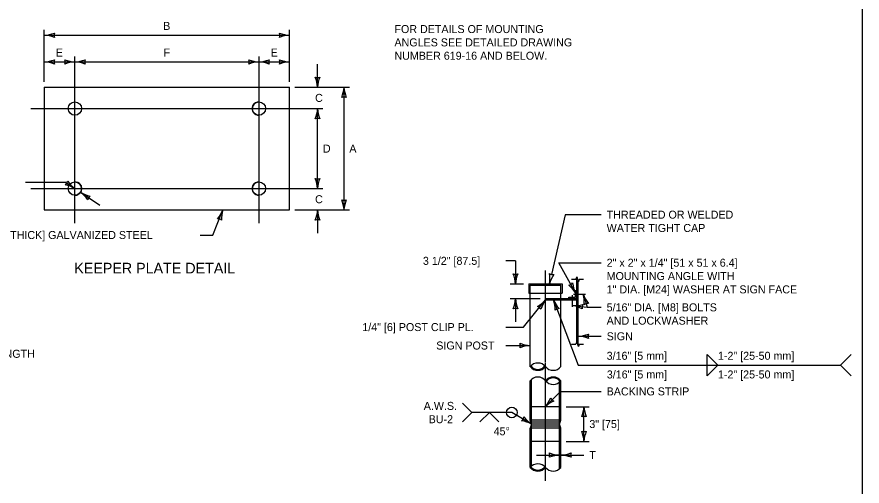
# Model space of a CAD drawing. Extents: x 49991 to 81321, y 49988 to 50028.
# Drawn here: x 50010.41 to 50016.75, y 49992.49 to 49996.01 of the extents above; entities that cross this region are included whole.
import ezdxf

# ---------------------------------------------------------------- set-up
doc = ezdxf.new("R2010")
doc.units = 0
for name, color, linetype in [('Level 1', 7, 'Continuous'), ('Level 2', 7, 'Continuous'), ('Level 3', 7, 'Continuous'), ('Level 4', 7, 'Continuous'), ('Level 5', 7, 'Continuous'), ('Level 6', 7, 'Continuous')]:
    doc.layers.add(name, color=color, linetype=linetype)

msp = doc.modelspace()

# ---------------------------------------------------------------- linework, layer by layer
at = {"layer": 'Level 1'}
for p, q in [((50010.6168, 49995.4787), (50012.4568, 49995.4787)), ((50010.6168, 49995.4787), (50010.6168, 49994.5587)), ((50012.4568, 49994.5587), (50012.4568, 49995.4787)), ((50010.6168, 49994.5587), (50012.4568, 49994.5587)), ((50014.6111, 49993.566), (50014.6111, 49994.0526)), ((50014.2511, 49994.0033), (50014.5011, 49994.0033)), ((50014.2511, 49994.0033), (50014.2511, 49993.9333)), ((50014.5011, 49994.0033), (50014.5011, 49993.9333)), ((50014.6211, 49993.5378), (50014.6211, 49994.0244)), ((50014.2511, 49993.9333), (50014.5011, 49993.9333)), ((50014.2611, 49993.3829), (50014.2611, 49993.9333)), ((50014.2611, 49993.3829), (50014.2611, 49993.9333)), ((50014.2611, 49993.3829), (50014.2611, 49993.9333)), ((50014.2611, 49993.3829), (50014.2611, 49993.9333)), ((50014.4911, 49993.3832), (50014.4911, 49993.9333)), ((50014.5857, 49993.9255), (50014.6761, 49993.9255)), ((50014.6011, 49993.9033), (50014.6011, 49993.9533)), ((50014.6011, 49993.9533), (50014.6111, 49993.9533)), ((50014.3761, 49993.8933), (50014.6111, 49993.8933)), ((50014.3761, 49993.8833), (50014.3761, 49993.8933)), ((50014.3761, 49993.8833), (50014.6111, 49993.8833)), ((50014.5511, 49993.9033), (50014.6011, 49993.9033)), ((50014.5511, 49993.8933), (50014.5511, 49993.9033)), ((50014.5785, 49993.8322), (50014.5785, 49993.9189)), ((50014.2611, 49992.9827), (50014.2611, 49993.2777)), ((50014.4911, 49992.9827), (50014.491, 49993.2778)), ((50014.4911, 49992.9827), (50014.2611, 49992.9827)), ((50014.2711, 49992.9527), (50014.2611, 49992.9827)), ((50014.4811, 49992.9527), (50014.4911, 49992.9827)), ((50014.2711, 49992.9527), (50014.2611, 49992.9227)), ((50014.4911, 49992.9227), (50014.2611, 49992.9227)), ((50014.2611, 49992.6274), (50014.2611, 49992.9227)), ((50014.4811, 49992.9677), (50014.2711, 49992.9677)), ((50014.4811, 49992.9527), (50014.2711, 49992.9527)), ((50014.4811, 49992.9377), (50014.2711, 49992.9377)), ((50014.4911, 49992.9227), (50014.4811, 49992.9527)), ((50014.4911, 49992.6276), (50014.4911, 49992.9227))]:
    msp.add_line(p, q, dxfattribs=at)
msp.add_lwpolyline([(49999.3835, 49998.9992), (50016.7501, 49998.9992), (50016.7501, 49987.7988), (49999.3835, 49987.7988)], close=True, dxfattribs=at)
for centre in [(50010.8468, 49995.3187), (50012.2268, 49995.3187), (50010.8468, 49994.7187), (50012.2268, 49994.7187)]:
    msp.add_circle(centre, 0.05, dxfattribs=at)
for centre, radius, start, end in [((50012.2268, 49995.3187), 0.05, 90, 273.45431), ((50010.8468, 49994.7187), 0.05, 270, 93.45431), ((50012.2268, 49994.7187), 0.05, 90, 273.45431), ((50014.3186, 49993.3362), 0.0741, 39.17071, 140.92889), ((50014.3186, 49993.4298), 0.0741, 219.17071, 320.82929), ((50014.3186, 49993.4298), 0.0673, 218.24875, 321.75125), ((50014.4335, 49993.4298), 0.0741, 219.17071, 321.00882), ((50014.3185, 49993.231), 0.0741, 39.11604, 140.90495), ((50014.4335, 49993.231), 0.0741, 39.11604, 140.88396), ((50014.4335, 49993.231), 0.0672, 38.18255, 141.81745), ((50014.4335, 49993.3245), 0.0741, 219.11604, 320.88396), ((50014.3186, 49992.5806), 0.0741, 39.17071, 140.85983), ((50014.3186, 49992.6742), 0.0741, 219.14017, 320.82929), ((50014.3186, 49992.6742), 0.0673, 218.24684, 321.74095), ((50014.4335, 49992.6742), 0.0741, 219.17071, 321.0128)]:
    msp.add_arc(centre, radius, start, end, dxfattribs=at)
at = {"layer": 'Level 3'}
for p, q in [((50010.6168, 49995.5187), (50010.6168, 49995.9087)), ((50012.4568, 49995.5187), (50012.4568, 49995.9087)), ((50010.6168, 49995.8687), (50012.4568, 49995.8687)), ((50010.6168, 49995.6687), (50010.8468, 49995.6687)), ((50010.8468, 49995.6687), (50012.2282, 49995.6687)), ((50012.2282, 49995.6687), (50012.4568, 49995.6687)), ((50012.6664, 49995.4787), (50012.6664, 49995.6521)), ((50012.4968, 49995.4787), (50012.9047, 49995.4787)), ((50012.8647, 49994.5587), (50012.8647, 49995.4787)), ((50012.6664, 49994.7187), (50012.6664, 49995.3187)), ((50010.475, 49994.7658), (50010.776, 49994.7658)), ((50010.776, 49994.7658), (50010.8468, 49994.7187)), ((50010.8884, 49994.691), (50011.0328, 49994.595)), ((50011.8813, 49994.3703), (50011.9562, 49994.5587)), ((50012.4968, 49994.5587), (50012.9047, 49994.5587)), ((50012.6664, 49994.5587), (50012.6664, 49994.3853)), ((50014.5229, 49994.523), (50014.4219, 49994.075)), ((50014.7945, 49994.523), (50014.5229, 49994.523)), ((50011.7853, 49994.3703), (50011.8813, 49994.3703)), ((50014.1511, 49994.1767), (50014.0787, 49994.1767)), ((50014.1511, 49994.1767), (50014.1511, 49994.0033)), ((50014.601, 49993.936), (50014.4767, 49994.1626)), ((50014.4767, 49994.1626), (50014.7945, 49994.1626)), ((50014.1111, 49994.0033), (50014.2111, 49994.0033)), ((50014.6596, 49993.9255), (50014.6895, 49993.828)), ((50014.1111, 49993.8933), (50014.3361, 49993.8933)), ((50014.1511, 49993.8933), (50014.1511, 49993.7199)), ((50014.2115, 49993.6799), (50014.3761, 49993.8833)), ((50014.4365, 49993.8833), (50014.62, 49993.3946)), ((50014.5785, 49993.8425), (50014.6895, 49993.828)), ((50014.6895, 49993.828), (50014.7945, 49993.828)), ((50014.0787, 49993.6799), (50014.2115, 49993.6799)), ((50014.6211, 49993.6109), (50014.7945, 49993.6109)), ((50014.0787, 49993.5416), (50014.2611, 49993.5417)), ((50014.0787, 49993.5416), (50014.1588, 49993.5416)), ((50015.5891, 49993.3146), (50015.5891, 49993.4746)), ((50015.5891, 49993.4746), (50015.6691, 49993.3946)), ((50016.5872, 49993.3946), (50016.6672, 49993.4746)), ((50014.62, 49993.3946), (50016.5872, 49993.3946)), ((50015.5891, 49993.3146), (50015.6691, 49993.3946)), ((50016.5872, 49993.3946), (50016.6672, 49993.3146)), ((50014.4877, 49993.1974), (50014.3731, 49993.0827)), ((50014.4877, 49993.1974), (50014.7945, 49993.1974)), ((50013.8231, 49993.0389), (50013.7524, 49993.1096)), ((50013.8231, 49993.0389), (50013.7524, 49992.9682)), ((50014.1237, 49993.0389), (50013.8231, 49993.0389)), ((50013.9547, 49993.0389), (50013.884, 49992.9682)), ((50014.0254, 49992.9682), (50013.9547, 49993.0389)), ((50014.2711, 49992.9527), (50014.1237, 49993.0389)), ((50014.5311, 49993.0827), (50014.7045, 49993.0827)), ((50014.6645, 49992.8227), (50014.6645, 49993.0827)), ((50014.5311, 49992.8227), (50014.7045, 49992.8227)), ((50014.3077, 49992.7202), (50014.4811, 49992.7202)), ((50014.4911, 49992.7202), (50014.6645, 49992.7202))]:
    msp.add_line(p, q, dxfattribs=at)
msp.add_circle((50014.1237, 49993.0389), 0.04, dxfattribs=at)
for centre, radius, start, end in [((50010.6053, 49996.1014), 0.233, 272.82731, 292.07716), ((50010.745, 49995.8687), 0.0548, 162.13882, 197.86118), ((50012.4659, 49996.0908), 0.2223, 247.45601, 267.63952), ((50012.3286, 49995.8687), 0.0548, 342.13882, 17.86118), ((50010.6076, 49995.6466), 0.2223, 67.45601, 87.63952), ((50012.4683, 49995.636), 0.233, 92.82731, 112.07716), ((50010.6053, 49995.9014), 0.233, 272.82731, 292.07716), ((50010.6076, 49995.4466), 0.2223, 67.45601, 87.63952), ((50010.745, 49995.6687), 0.0548, 162.13882, 197.86118), ((50010.8559, 49995.8908), 0.2223, 247.45601, 267.63952), ((50010.7186, 49995.6687), 0.0548, 342.13882, 17.86118), ((50010.8583, 49995.436), 0.233, 92.82731, 112.07716), ((50010.8353, 49995.9014), 0.233, 272.82731, 292.07716), ((50010.8376, 49995.4466), 0.2223, 67.45601, 87.63952), ((50010.975, 49995.6687), 0.0548, 162.13882, 197.86118), ((50012.2359, 49995.8908), 0.2223, 247.45601, 267.63952), ((50012.0986, 49995.6687), 0.0548, 342.13882, 17.86118), ((50012.2383, 49995.436), 0.233, 92.82731, 112.07716), ((50012.2153, 49995.9014), 0.233, 272.82731, 292.07716), ((50012.2176, 49995.4466), 0.2223, 67.45601, 87.63952), ((50012.355, 49995.6687), 0.0548, 162.13882, 197.86118), ((50012.4659, 49995.8908), 0.2223, 247.45601, 267.63952), ((50012.3286, 49995.6687), 0.0548, 342.13882, 17.86118), ((50012.4683, 49995.436), 0.233, 92.82731, 112.07716), ((50012.6664, 49995.6069), 0.0548, 252.13882, 287.86118), ((50012.4337, 49995.4672), 0.233, 2.82731, 22.07716), ((50012.8885, 49995.4695), 0.2223, 157.45601, 177.63952), ((50012.6426, 49995.4879), 0.2223, 337.45601, 357.63952), ((50013.0974, 49995.4902), 0.233, 182.82731, 202.07716), ((50012.8647, 49995.3505), 0.0548, 72.13882, 107.86118), ((50012.4443, 49995.3279), 0.2223, 337.45601, 357.63952), ((50012.8991, 49995.3302), 0.233, 182.82731, 202.07716), ((50012.6664, 49995.1905), 0.0548, 72.13882, 107.86118), ((50010.74, 49994.7897), 0.0548, 308.52207, 344.24443), ((50010.7275, 49994.5185), 0.233, 59.21056, 78.46041), ((50010.9774, 49994.8986), 0.2223, 213.83926, 234.02277), ((50012.6664, 49994.8469), 0.0548, 252.13882, 287.86118), ((50012.4337, 49994.7072), 0.233, 2.82731, 22.07716), ((50012.8885, 49994.7095), 0.2223, 157.45601, 177.63952), ((50010.7578, 49994.511), 0.2223, 33.85278, 54.03628), ((50011.0076, 49994.8912), 0.233, 239.22408, 258.47393), ((50010.9952, 49994.62), 0.0548, 128.53558, 164.25794), ((50012.8647, 49994.6869), 0.0548, 252.13882, 287.86118), ((50012.632, 49994.5472), 0.233, 2.82731, 22.07716), ((50013.0868, 49994.5495), 0.2223, 157.45601, 177.63952), ((50011.74, 49994.6457), 0.233, 318.83632, 338.08617), ((50012.1691, 49994.4947), 0.2223, 163.27396, 183.45747), ((50012.4443, 49994.5679), 0.2223, 337.45601, 357.63952), ((50012.8991, 49994.5702), 0.233, 182.82731, 202.07716), ((50011.9142, 49994.4375), 0.0548, 53.0523, 88.77466), ((50012.6664, 49994.4305), 0.0548, 72.13882, 107.86118), ((50014.1511, 49994.1315), 0.0548, 252.13882, 287.86118), ((50013.9183, 49993.9918), 0.233, 2.82731, 22.07716), ((50014.3732, 49993.9942), 0.2223, 157.45601, 177.63952), ((50014.1762, 49994.0433), 0.233, 350.12207, 9.37192), ((50014.6204, 49993.9455), 0.2223, 144.75077, 164.93428), ((50014.4339, 49994.1284), 0.0548, 239.43358, 275.15594), ((50014.5394, 49994.0483), 0.0548, 280.87536, 316.59773), ((50014.4025, 49993.8139), 0.233, 31.56386, 50.81371), ((50014.8002, 49994.0347), 0.2223, 186.19256, 206.37606), ((50014.4445, 49993.8691), 0.2223, 354.51079, 14.6943), ((50014.8787, 49994.0048), 0.233, 199.88209, 219.13194), ((50013.9289, 49993.9025), 0.2223, 337.45601, 357.63952), ((50014.3838, 49993.9048), 0.233, 182.82731, 202.07716), ((50014.2091, 49994.0302), 0.2223, 298.48321, 318.66671), ((50014.5642, 49993.7459), 0.233, 143.85451, 163.10436), ((50014.2253, 49993.8138), 0.2223, 358.03153, 18.21504), ((50014.6503, 49993.9759), 0.233, 203.40283, 222.65268), ((50014.6972, 49993.803), 0.0548, 89.1936, 124.91596), ((50014.1511, 49993.7651), 0.0548, 72.13882, 107.86118), ((50014.2954, 49993.7837), 0.0548, 33.16601, 68.88837), ((50014.4816, 49993.7633), 0.0548, 92.71434, 128.4367), ((50014.5972, 49994.0748), 0.233, 265.3948, 284.64465), ((50014.5406, 49993.6234), 0.2223, 60.0235, 80.20701), ((50014.7056, 49993.8259), 0.0548, 154.70631, 190.42867), ((50014.6096, 49993.8436), 0.233, 272.82731, 292.07716), ((50014.6119, 49993.3888), 0.2223, 67.45601, 87.63952), ((50014.7493, 49993.6109), 0.0548, 162.13882, 197.86118), ((50014.2702, 49993.7638), 0.2223, 247.46964, 267.65315), ((50014.1328, 49993.5416), 0.0548, 342.15245, 17.87481), ((50014.2726, 49993.309), 0.233, 92.84094, 112.09079), ((50014.2003, 49993.2391), 0.233, 317.85337, 337.10322), ((50014.5237, 49992.9193), 0.2223, 112.48207, 132.66558), ((50014.4637, 49993.1734), 0.0548, 207.16487, 242.88724), ((50014.4423, 49993.0919), 0.2223, 337.45601, 357.63952), ((50014.8972, 49993.0942), 0.233, 182.82731, 202.07716), ((50014.1604, 49993.0175), 0.0548, 311.81958, 347.54194), ((50014.1635, 49992.746), 0.233, 62.50807, 81.75793), ((50014.3911, 49993.1399), 0.2223, 217.13678, 237.32028), ((50014.6645, 49992.9545), 0.0548, 72.13882, 107.86118), ((50014.6645, 49992.9509), 0.0548, 252.13882, 287.86118), ((50014.4317, 49992.8112), 0.233, 2.82731, 22.07716), ((50014.8866, 49992.8136), 0.2223, 157.45601, 177.63952), ((50014.4902, 49992.9424), 0.2223, 247.45601, 267.63952), ((50014.3528, 49992.7202), 0.0548, 342.13882, 17.86118), ((50014.4925, 49992.4875), 0.233, 92.82731, 112.07716), ((50014.4796, 49992.9529), 0.233, 272.82731, 292.07716), ((50014.4819, 49992.4981), 0.2223, 67.45601, 87.63952), ((50014.6193, 49992.7202), 0.0548, 162.13882, 197.86118)]:
    msp.add_arc(centre, radius, start, end, dxfattribs=at)
at = {"layer": 'Level 4'}
for p, q in [((50014.2611, 49993.9333), (50014.2611, 49993.9933)), ((50014.2611, 49993.9933), (50014.4911, 49993.9933)), ((50014.4911, 49993.9333), (50014.4911, 49993.9933)), ((50014.6111, 49993.8833), (50014.6111, 49993.8933)), ((50014.2711, 49992.6397), (50014.2711, 49993.2873)), ((50014.4811, 49992.6204), (50014.4811, 49993.2681)), ((50014.4811, 49993.0827), (50014.2711, 49993.0827)), ((50014.4811, 49992.8227), (50014.2711, 49992.8227))]:
    msp.add_line(p, q, dxfattribs=at)
at = {"layer": 'Level 5'}
for p, q in [((50010.8468, 49994.4587), (50010.8468, 49995.7087)), ((50012.2268, 49995.7087), (50012.2268, 49994.4587)), ((50010.5168, 49995.3187), (50012.7064, 49995.3187)), ((50010.5168, 49994.7187), (50012.7064, 49994.7187)), ((50014.3761, 49993.4194), (50014.3761, 49994.1033)), ((50014.3761, 49992.5274), (50014.3761, 49993.415))]:
    msp.add_line(p, q, dxfattribs=at)
at = {"layer": 'Level 6'}
for p, q in [((50014.6096, 49994.0568), (50014.6031, 49994.0385)), ((50014.6096, 49994.0568), (50014.6161, 49994.0385)), ((50014.5711, 49994.0385), (50014.6031, 49994.0385)), ((50014.6161, 49994.0385), (50014.6226, 49994.0202)), ((50014.6291, 49994.0385), (50014.6226, 49994.0202)), ((50014.6291, 49994.0385), (50014.6611, 49994.0385)), ((50014.5711, 49993.5519), (50014.6031, 49993.5519)), ((50014.6096, 49993.5702), (50014.6031, 49993.5519)), ((50014.6096, 49993.5702), (50014.6161, 49993.5519)), ((50014.6161, 49993.5519), (50014.6226, 49993.5336)), ((50014.6291, 49993.5519), (50014.6226, 49993.5336)), ((50014.6291, 49993.5519), (50014.6611, 49993.5519))]:
    msp.add_line(p, q, dxfattribs=at)

# ---------------------------------------------------------------- texts
at = {"layer": 'Level 2'}
for s, height, p in [('B', 0.06, (50011.5091, 49995.9087)), ('FOR DETAILS OF MOUNTING', 0.06, (50013.243, 49995.8851)), ('ANGLES SEE DETAILED DRAWING', 0.06, (50013.243, 49995.7851)), ('E', 0.06, (50010.7031, 49995.7087)), ('F', 0.06, (50011.5113, 49995.7087)), ('E', 0.06, (50012.3145, 49995.7087)), ('NUMBER 619-16 AND BELOW.', 0.06, (50013.243, 49995.6851)), ('C', 0.06, (50012.6479, 49995.3687)), ('D', 0.06, (50012.7064, 49994.9886)), ('A', 0.06, (50012.9047, 49994.9887)), ('C', 0.06, (50012.6479, 49994.6087)), ('THREADED OR WELDED', 0.06, (50014.8345, 49994.493)), ('WATER TIGHT CAP', 0.06, (50014.8345, 49994.393)), ('28 GAUGE [0.5 mm THICK] GALVANIZED STEEL', 0.06, (50009.6251, 49994.3403)), ('3 1/2" [87.5]', 0.06, (50013.4566, 49994.1467)), ('2" x 2" x 1/4" [51 x 51 x 6.4]', 0.06, (50014.8345, 49994.1326)), ('KEEPER PLATE DETAIL', 0.08, (50010.8422, 49994.082)), ('MOUNTING ANGLE WITH', 0.06, (50014.8345, 49994.0326)), ('1" DIA. [M24] WASHER AT SIGN FACE', 0.06, (50014.8345, 49993.9326)), ('5/16" DIA. [M8] BOLTS', 0.06, (50014.8345, 49993.798)), ('AND LOCKWASHER', 0.06, (50014.8345, 49993.698)), ('1/4" [6] POST CLIP PL.', 0.06, (50013.0019, 49993.6499)), ('SIGN', 0.06, (50014.8345, 49993.5809)), ('SIGN POST', 0.06, (50013.5565, 49993.5116)), ('SEE ELEVATIONS FOR LENGTH', 0.06, (50009.3202, 49993.4496)), ('3/16" [5 mm]', 0.06, (50014.8345, 49993.4346)), ('1-2" [25-50 mm]', 0.06, (50015.6691, 49993.4346)), ('3/16" [5 mm]', 0.06, (50014.8356, 49993.2946)), ('1-2" [25-50 mm]', 0.06, (50015.6691, 49993.2946)), ('BACKING STRIP', 0.06, (50014.8345, 49993.1674)), ('A.W.S.', 0.06, (50013.4627, 49993.0589)), ('BU-2 ', 0.06, (50013.4996, 49992.9589)), ('3" [75]', 0.06, (50014.7045, 49992.9227)), ('45° ', 0.06, (50013.9868, 49992.8682)), ('T', 0.06, (50014.7045, 49992.6902))]:
    msp.add_text(s, height=height, dxfattribs=at).set_placement(p)

doc.saveas('drawing.dxf')
